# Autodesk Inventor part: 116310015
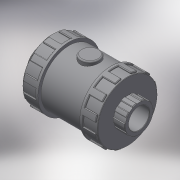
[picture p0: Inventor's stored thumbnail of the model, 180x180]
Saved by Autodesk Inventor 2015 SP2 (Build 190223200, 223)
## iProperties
Created: 2017-11
Part Number: 116310015
Material: Generic
Description: PLASSON AIR RELEASE VALVE THR PVC 1.1/2"
Document SubType Name: Modeling
Designer: KIM
Density: 1 g/cm^3
Appearance: Default
Author: KIM
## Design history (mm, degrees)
derived "116310 - 116910.ipt"
feature "Solid1::116310 - 116910.ipt"
tag "TaggingFeature1"
body "Solid1"
other parameters: "d0" = 142, "d1" = 44.845, "d2" = 96, "d3" = 22, "d4" = 35.876, "d5" = 15.4, "d7" = 62.783, "d8" = 86.4, "d13" = 1.34535, "d23" = 22, "d24" = 92.16, "d25" = 0.8969, "d26" = 1.34535, "d27" = 14.4, "d28" = 7.2, "d29" = 16.5, "d30" = 0, "d35" = 1.34535, "d39" = 48, "d45" = 360 deg, "d47" = 0.8969, "d50" = 48, "d51" = 28.8, "d53" = 0, "d54" = 1.92, "d55" = 8.969, "d56" = 4.4845, "d58" = 0, "d59" = 1.34535, "d61" = 360 deg, "G_" = 44.845, "l_" = 22, "H_" = 142, "K_" = 96
